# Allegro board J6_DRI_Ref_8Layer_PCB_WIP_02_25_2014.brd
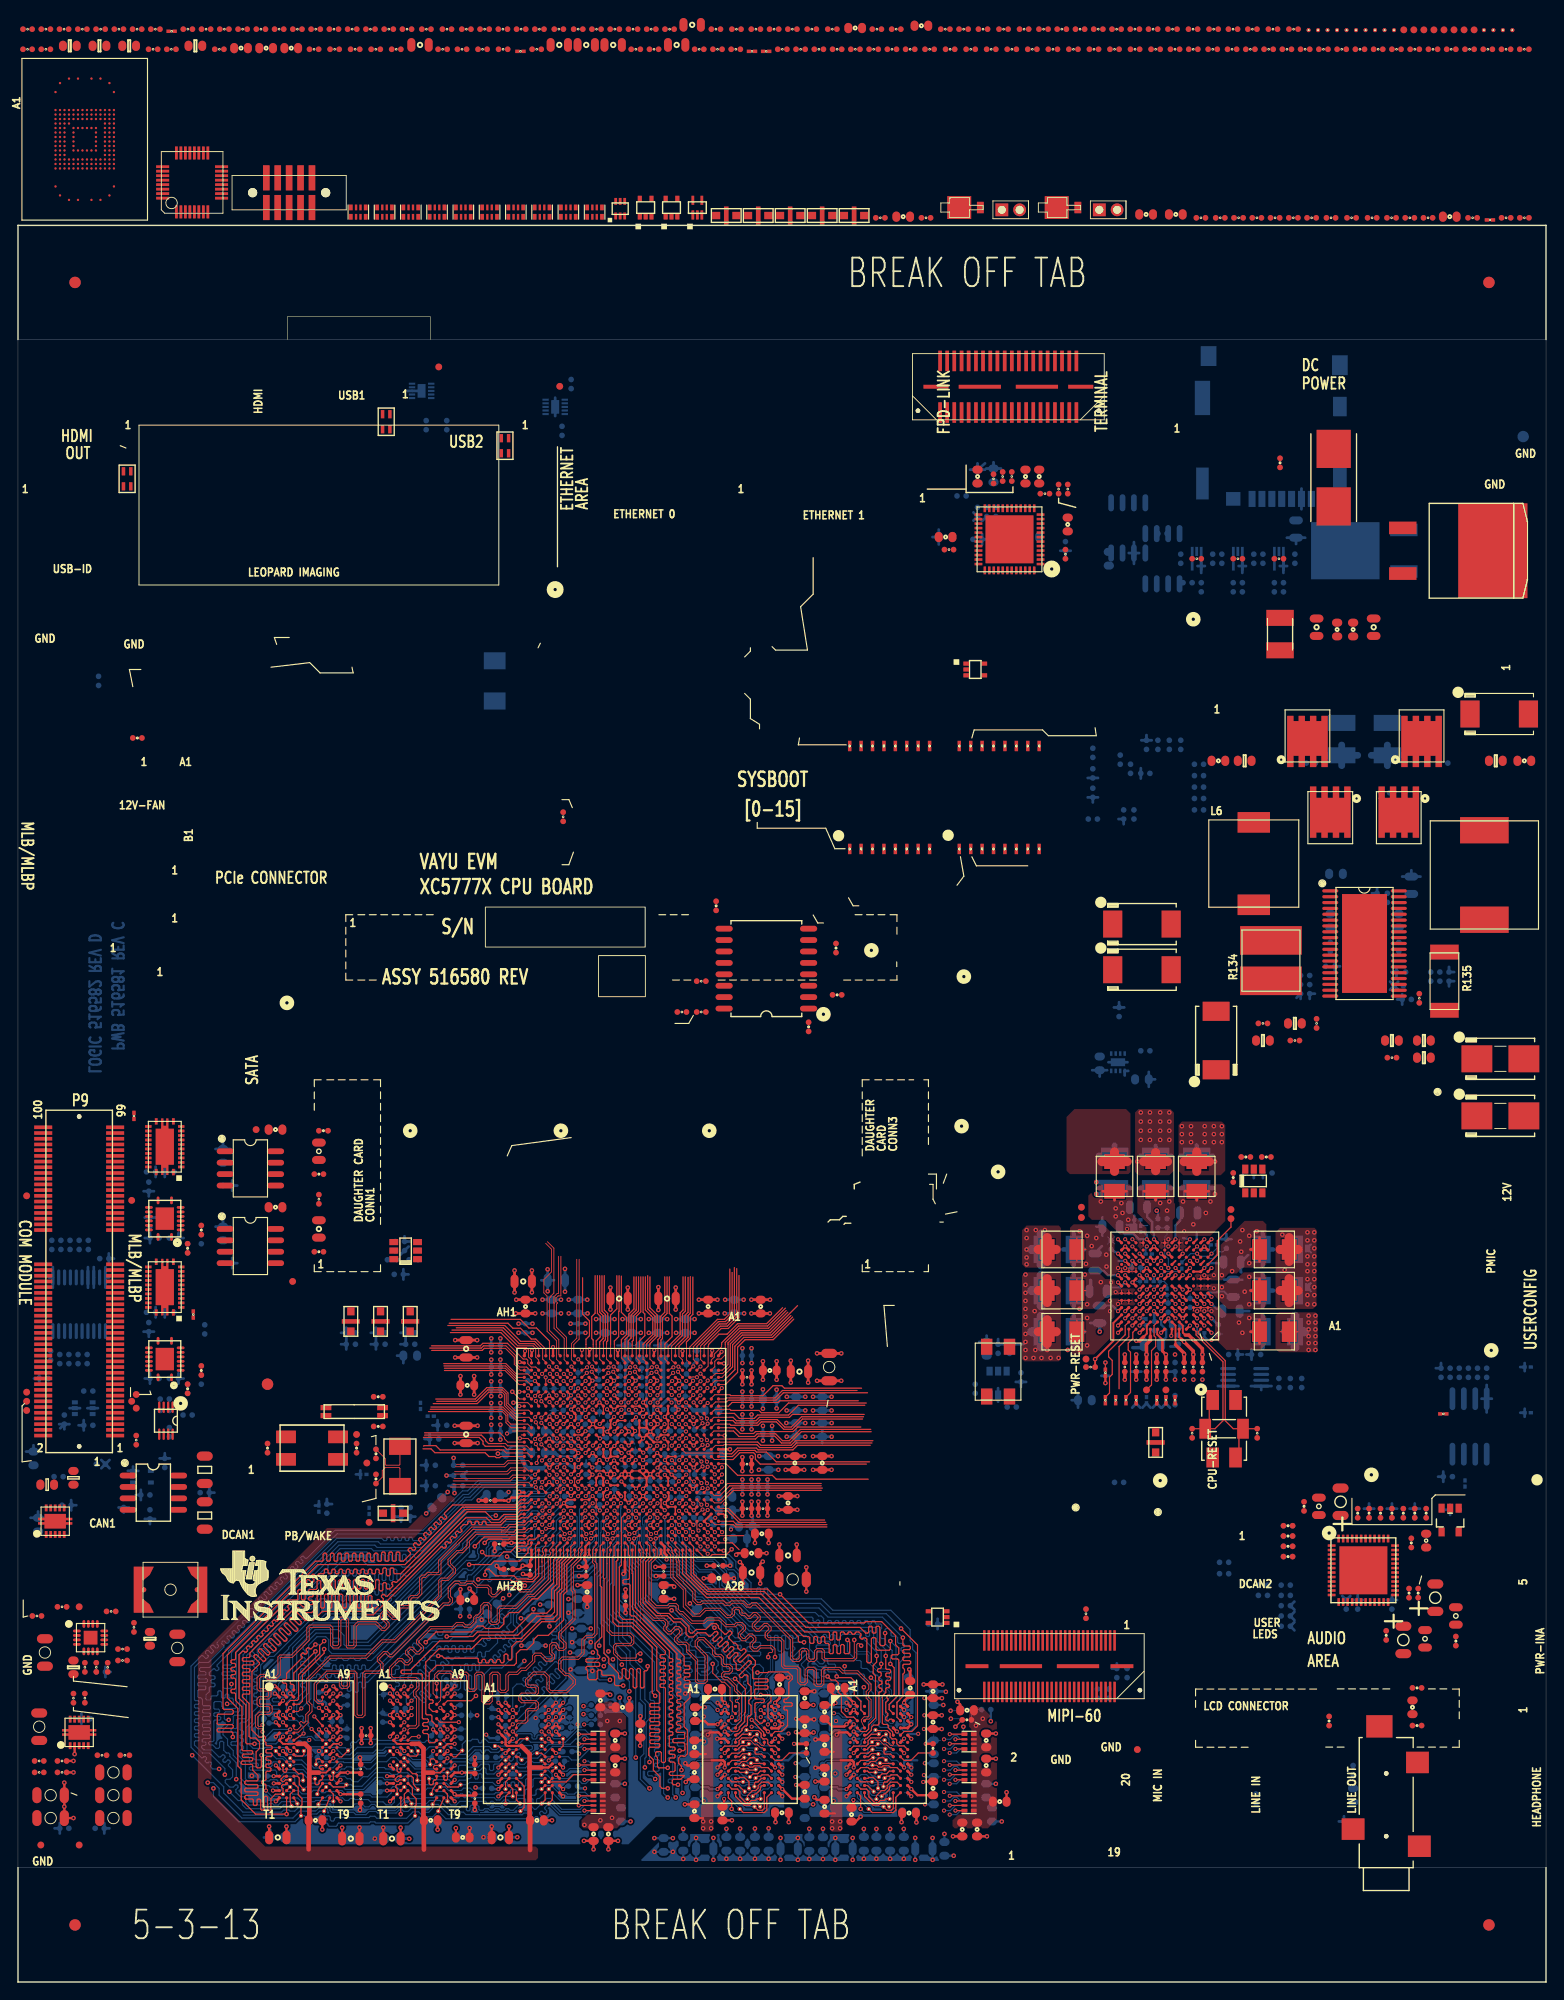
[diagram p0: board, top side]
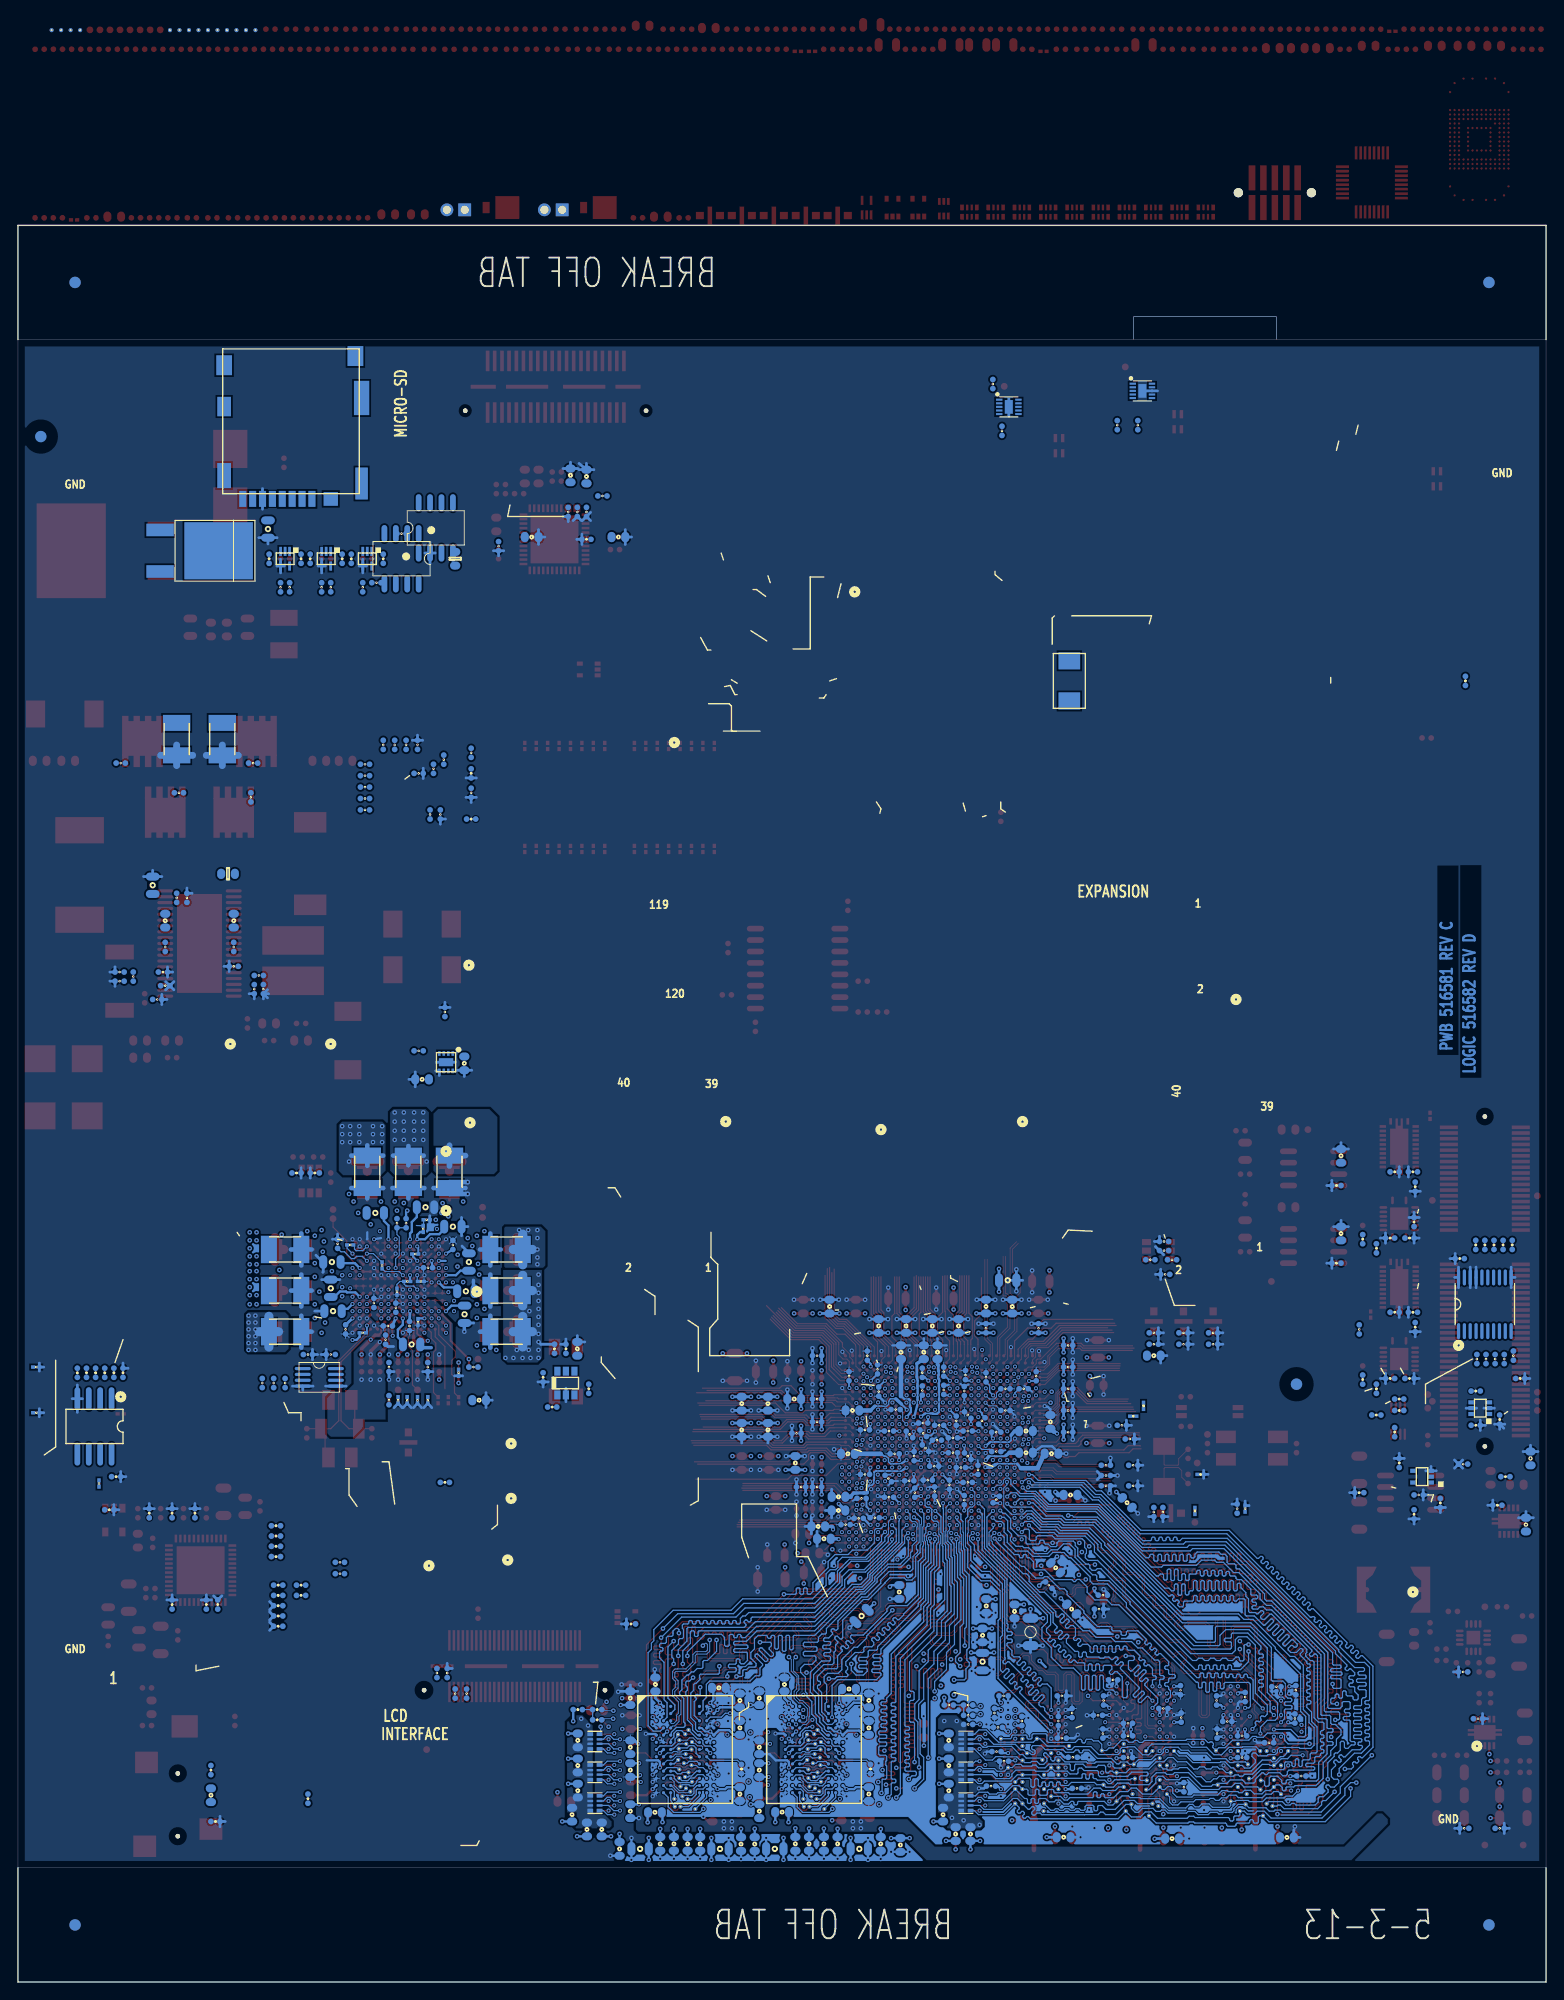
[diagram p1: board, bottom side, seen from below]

Outline 170 x 195.4 mm; copper layers: TOP, L2-GND1, L3-SIGNAL, L4-PWR1, L5-PWR2, L6-SIGNAL, L7-GND2, BOTTOM. Coordinates in mm from the lower left corner of the outline.
Outline path: 0,182.7 0,195.4 170,195.4 170,182.7 ; 0,182.7 0,12.7 ; 0,182.7 170,182.7 ; 0,12.7 0,0 170,0 170,12.7 ; 0,12.7 170,12.7 ; 170,12.7 170,182.7 ; 30,182.7 30,185.24 45.88,185.24 45.88,182.7

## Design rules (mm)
net group CON_USB1_DM: nets CON_USB1_DM H_USB1_DM
net group CON_USB1_DP: nets CON_USB1_DP H_USB1_DP
net group CON_USB2_DM: nets CON_USB2_DM H_USB2_DM
net group CON_USB2_DP: nets CON_USB2_DP H_USB2_DP
net group CPU_HDMI_TX0: nets H_HDMI_TX0+ H_HDMI_TX0-
net group CPU_HDMI_TX1: nets H_HDMI_TX1+ H_HDMI_TX1-
net group CPU_HDMI_TXC: nets H_HDMI_TXC+ H_HDMI_TXC-
net group DIFFPAIR0: nets H_DDR1_CLK0 H_DDR1_CLK0N
net group DIFFPAIR1: nets H_DDR1_DQS0 H_DDR1_DQSN0
net group DIFFPAIR2: nets H_DDR1_DQS1 H_DDR1_DQSN1
net group DIFFPAIR3: nets H_DDR1_DQS2 H_DDR1_DQSN2
net group DIFFPAIR4: nets H_DDR1_DQS3 H_DDR1_DQSN3
net group DIFFPAIR5: nets H_DDR1_DQS_ECC H_DDR1_DQSN_ECC
net group DIFFPAIR6: nets H_DDR2_CLK0 H_DDR2_CLK0N
net group DIFFPAIR7: nets H_DDR2_DQS3 H_DDR2_DQSN3
net group DIFFPAIR8: nets H_DDR2_DQS2 H_DDR2_DQSN2
net group DIFFPAIR9: nets H_DDR2_DQS1 H_DDR2_DQSN1
net group DIFFPAIR10: nets H_DDR2_DQS0 H_DDR2_DQSN0
net group HDMI_TX2: nets H_HDMI_TX2+ H_HDMI_TX2-
net group 100-OHM: nets H_MLBP_DAT_N H_MLBP_DAT_P H_MLBP_SIG_N H_MLBP_SIG_P H_OSC0_XIN H_OSC0_XOUT H_OSC1_RTN H_OSC1_XOUT H_OSCRTC_XIN H_OSCRTC_XOUT
net group CLK-2X: nets AIC_BCLK AIC_MCA3_ACLKX AIC_WCLK COMQ_MMC0_CLK CON_MMC1_CLK FM_I2S_CLK H_MLBP_CLK_N H_MLBP_CLK_P MCA1_ACLKX MCA7_CLKX MMC2_CLK MMC4_CLK PCM_CLK PMIC_32K_CLKOUT SLEEP_CLK
net group H_QSPI1_RTCLK: nets H_QSPI1_RTCLK H_QSPI1_SCLK_23254155 H_QSPI1_SCLK_S1_23254130
net group PWR_PH: nets H_USB1_DRV_VBUS H_USB2_DRV_VBUS N16995143 N17213676 N17213686 N17213736 N17213790 N17213808 N17213830 N17213836 N17213987 N17214061 N17214151 N17214159 N17214195 N17214201 N17214255 N17214311 N17214457 N17214615 N17214651 N17444583 N17444631 N17444633 N17444649 N17551928 N18507369 N18740603 N18740978 N18743331 N18763016 N18763017 N18763021 N19176689 N19176787 N21135894 N21136029 N21136035 N21136037 N21136043 N21136051 N21136104 N21136106 N21136118 N21136820 N21137001 N21137040 N21137042 N21137044 N21411928 N25164864 N25164868 N32742919 N32835273 N32916975 N33161549 N46501256 N167456600 N167457561 PMIC_GPIO_1 VAIC_AVDD_DAC3V3 VAIC_DRVDD_3V3 VAIC_DVDD_1V8 VAIC_IOVDD_3V3 VBUS_USB1_SW VBUS_USB2_SW VCAP_VBBLDO_GPU VCAP_VBBLDO_IVA VCAP_VBBLDO_MPU VCAP_VDDRAM_CORE1 VCAP_VDDRAM_CORE2 VCAP_VDDRAM_CORE3 VCAP_VDDRAM_CORE4 VCAP_VDDRAM_CORE5 VCAP_VDDRAM_DSPEVE1 VCAP_VDDRAM_DSPEVE2 VCAP_VDDRAM_IVA VCAP_VDDRAM_MPU1 VCAP_VDDRAM_MPU2 VDAC_3V3 VDDA_IVA_1V8 VDDA_PCI_1P8 VDDA_PHY_1V8 VDDA_PLL_1V8 VDDA_RTC VDDA_SATA_1P8 VDDSHV5 VDDSHV8 VMMC_3V3 VUSB_3V3
net group PWR_SP: nets EVM_12V GA1 GA2 GB1 GB2 H_POR_N LVL_SHIFT_V N17043188 N17213838 N17214057 N17214229 N17214562 N17214601 N17551455 N17681908 N18763019 N45361223 N45364158 PHA PHB TPS43351_GC2 VBUS_USB1 VBUS_USB2 VDDA_ANA VDDA_DEBUG_1V8 VDDA_HDMI VDDA_MPU_1V8 VDDA_VIDEO_1V8 VEVM_3V6 VEVM_5V0
net group VIDEO+: nets N21266752 N21266767 VIDEO+
net group VIDEO-: nets N21266761 N21266764 VIDEO-
nets with their own width: min track width 0.305; nets VEVM_3V3

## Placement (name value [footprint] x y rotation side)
C5  0.1uF  [C402-25]  109.55 167.46 90 top
C6  0.1uF  [C402-25]  110.57 167.46 90 top
C7  4.7uF  [C603-35X45]  112.09 167.46 90 top
C8  4.7uF  [C603-35X45]  113.61 167.46 90 top
C13  4.7uF  [C603-35X45]  116.79 162.13 90 top
C14  0.1uF  [C402-25]  131.14 158.32 0 top
C15  0.1uF  [C402-25]  135.71 158.32 0 top
C16  0.1uF  [C402-25]  140.28 158.32 0 top
C45  0.1uF  [C603-35X45]  146.76 150.45 90 top
C47  1uF  [C805-35X60]  144.48 150.7 90 top
C49  0.1uF  [C603-35X45]  148.54 150.45 90 top
C50  1uF  [C805-35X60]  150.83 150.7 90 top
C51  100uF,16V  [C7343-84X118]  164.8 141.05 0 top
C52  4.7uF  [C1210-70X102]  140.41 149.94 90 top
C60  330pF  [C603-35X45]  133.55 135.84 0 top
C61  330pF  [C603-35X45]  167.59 135.84 180 top
C62  22uF,25V, x5R  [C1210-70X102]  147.27 138.25 90 bottom
C63  22uF,25V, x5R  [C1210-70X102]  152.35 138.25 90 bottom
C67  0.1uF  [C402-25]  91.14 109.81 0 top
C71  100uF 10V  [C7343-84X118]  125.04 112.6 0 top
C72  47UF 16V  [C1210-C7343-DUAL]  164.92 102.69 0 top
C74  100uF 10V  [C7343-84X118]  133.3 104.73 90 top
C76  100pF  [C402-25]  142.06 104.73 180 top
C77  47UF 16V  [C1210-C7343-DUAL]  164.92 96.34 0 top
C78  100pF  [C402-25]  152.86 102.82 0 top
C79  10uF  [C603-35X45]  28.65 94.82 180 top
C80  0.1uF  [C402-25]  33.99 94.69 0 top
C86  10uF  [C603-35X45]  28.65 86.18 180 top
C87  0.1uF  [C402-25]  33.48 87.07 90 top
C89  0.1uF  [C402-6P6SPC]  56.46 72.72 90 bottom
C90  0.22uF  [C603-6P6SPC]  82.63 75.14 270 top
C91  1uF  [C603-6P6SPC]  89.48 61.42 90 bottom
C92  0.22uF  [C603-6P6SPC]  86.56 64.34 90 bottom
C93  0.47uF  [C603-6P6SPC]  86.44 57.74 90 top
C94  0.47uF  [C603-6P6SPC]  89.48 64.34 90 bottom
C95  1uF  [C603-6P6SPC]  86.56 61.42 90 bottom
C96  0.22uF  [C603-6P6SPC]  89.48 57.74 90 top
C99  2.2uF/0402/6.3V  [C402-25]  125.55 68.4 90 top
C100  0.1uF  [C402-25]  128.85 72.98 180 bottom
C101  2.2uF/0402/6.3V  [C402-25]  129.74 68.4 270 top
C102  2.2uF/0402/6.3V  [C402-25]  130.76 68.4 90 top
C103  2.2uF/0402/6.3V  [C402-25]  131.78 68.4 90 top
C104  10uF  [C805-35X60]  73.28 215.47 0 top
C105  2.2uF  [C603-6P6SPC]  83.64 68.02 180 top
C106  33pF  [C402-25]  40.08 65.1 180 top
C107  0.1uF  [C402-6P6SPC]  81.1 64.85 0 bottom
C108  0.47uF  [C603-6P6SPC]  49.99 66.37 0 top
C109  0.1uF  [C402-6P6SPC]  72.36 63.68 0 bottom
C110  0.1uF  [C402-25]  47.19 61.93 180 bottom
C111  1uF  [C603-6P6SPC]  56.46 75.14 270 top
C112  0.1uF  [C402-6P6SPC]  61.16 59.01 180 bottom
C113  33pF  [C402-25]  40.08 61.8 180 top
C115  12pF/0402/50V  [C402-25]  130.63 61.04 270 top
C116  12pF/0402/50V  [C402-25]  137.87 61.04 270 top
C117  0.1uF  [C402-25]  46.3 60.4 180 bottom
C118  0.1uF  [C402-6P6SPC]  53.16 70.82 180 bottom
C119  0.1uF  [C402-6P6SPC]  53.16 63.58 180 bottom
C123  18 pF  [C402-25]  27.76 59.39 90 top
C124  18 pF  [C402-25]  37.67 59.39 270 top
C126  18 pF  [C402-25]  39.83 58.75 270 top
C128  18 pF  [C402-25]  39.83 55.96 90 top
C130  10uF  [C1206-40X70-POL]  147.14 53.42 90 top
C131  0.1uF  [C402-25]  143.08 52.91 270 top
C132  0.1uF  [C402-25]  149.05 52.15 90 top
C133  4.7uF  [C603-35X45]  156.67 49.1 90 top
C134  0.1uF  [C402-25]  155.02 48.85 90 top
C136  0.22uF  [C603-35X45]  63.32 43.39 270 top
C137  0.1uF  [C402-25]  53.54 48.72 180 top
C138  0.1uF  [C402-25]  56.97 45.8 270 top
C139  0.1uF  [C402-25]  63.2 45.67 270 top
C140  22uF  [C1206-40X70]  57.35 38.94 270 bottom
C141  0.1uF  [C402-25]  154.76 43.26 90 top
C142  0.1uF  [C402-25]  155.78 43.26 90 top
C143  0.1uF  [C402-25]  52.55 53.57 180 top
C144  10uF  [C1206-40X70-POL]  157.68 42.75 90 top
C147  0.1uF  [C402-25]  67.59 42.37 270 top
C148  0.1uF  [C402-25]  54.56 45.93 180 top
C149  0.1uF  [C402-25]  10.36 41.23 180 top
C150  NP  [C402-25]  12.9 39.45 270 top
C151  0.1uF  [C402-25]  152.22 38.56 270 top
C152  10uF  [C1206-40X70-POL]  154.13 38.05 270 top
C153  0.1uF  [C402-25]  159.97 37.92 270 top
C154  47uF  [C1206-40X70]  17.73 37.16 270 top
C155  4700pF  [C402-25]  11.63 37.04 0 top
C156  10uF  [C1206-40X70]  3 36.65 270 top
C157  12pF  [C402-25]  9.98 35 90 top
C158  0.22uF  [C603-35X45]  84.73 33.1 90 top
C159  0.22uF  [C603-35X45]  99.26 32.72 90 top
C160  0.22uF  [C603-35X45]  77.55 32.59 180 top
C161  0.22uF  [C603-35X45]  91.21 32.72 180 top
C162  0.22uF  [C603-35X45]  87.53 31.57 90 top
C163  0.22uF  [C603-35X45]  101.8 32.34 90 top
C164  0.22uF  [C603-35X45]  64.8 31.32 90 top
C165  0.22uF  [C603-35X45]  67.26 30.56 0 top
C166  0.22uF  [C603-35X45]  105.59 30.23 180 top
C167  0.22uF  [C603-35X45]  109.22 20.07 0 top
C168  2.2uF  [C603-35X45]  155.14 30.56 270 top
C169  0.22uF  [C603-35X45]  75.34 29.8 90 top
C170  0.22uF  [C603-35X45]  89.74 30.05 90 top
C171  0.22uF  [C603-35X45]  87.53 28.45 90 top
C172  0.22uF  [C603-35X45]  101.8 28.91 90 top
C173  0.1uF  [C402-25]  145.87 29.03 90 top
C174  10uF  [C1206-40X70]  2.36 28.4 90 top
C175  0.22uF  [C603-35X45]  66.45 26.88 90 top
C176  0.22uF  [C603-35X45]  107.72 26.88 90 top
C177  0.22uF  [C603-35X45]  75.26 26.11 90 top
C178  0.22uF  [C603-35X45]  89.74 26.37 90 top
C179  10pF  [C402-25]  11.89 25.22 180 top
C180  0.22uF  [C603-35X45]  66.45 24.08 90 top
C181  0.22uF  [C603-35X45]  107.72 24.08 90 top
C182  0.22uF  [C402-25]  38.13 23.7 90 top
C183  0.22uF  [C402-25]  50.83 23.7 90 top
C184  0.22uF  [C603-35X45]  75.26 23.32 90 top
C185  0.22uF  [C603-35X45]  89.74 23.07 90 top
C186  1000pF  [C402-25]  2.36 23.32 0 top
C187  0.001uF  [C402-25]  4.9 23.32 0 top
C188  10uF  [C1206-40X70]  10.62 23.32 180 top
C189  0.22uF  [C603-35X45]  87.53 21.16 90 top
C190  0.22uF  [C603-35X45]  101.8 21.54 90 top
C191  10uF  [C1206-40X70]  3.63 20.78 0 top
C192  10uF  [C1206-40X70]  10.62 20.78 180 top
C193  0.22uF  [C402-25]  38.13 20.4 270 top
C194  0.22uF  [C402-25]  50.83 20.4 270 top
C195  0.22uF  [C603-35X45]  84.99 18.82 0 top
C196  0.22uF  [C603-35X45]  99.14 18.8 0 top
C197  0.22uF  [C603-35X45]  75.26 19 90 top
C198  0.22uF  [C603-35X45]  89.74 19.51 90 top
C199  0.22uF  [C603-35X45]  78.38 18.75 270 top
C200  0.22uF  [C603-35X45]  92.74 18.62 270 top
C201  10uF  [C1206-40X70]  3.63 18.24 0 top
C202  10uF  [C1206-40X70]  10.62 18.24 180 top
C203  0.22uF  [C603-35X45]  33.1 17.99 0 top
C204  0.22uF  [C603-35X45]  45.92 17.99 0 top
C205  0.22uF  [C603-35X45]  57.73 17.99 0 top
C206  0.22uF  [C603-35X45]  64.03 16.46 270 top
C207  0.22uF  [C603-35X45]  65.68 16.46 270 top
C208  0.22uF  [C603-35X45]  105.05 16.97 270 top
C209  0.22uF  [C603-35X45]  106.71 16.97 270 top
C210  10uF  [C805-35X60]  28.91 16.08 180 top
C211  10uF  [C805-35X60]  37.03 15.95 0 top
C212  10uF  [C805-35X60]  41.61 15.95 180 top
C213  10uF  [C603-35X45]  49.48 16.08 0 top
C214  10uF  [C805-35X60]  53.67 16.08 180 top
C228  4.7uF  [C603-35X45]  108.53 167.59 90 bottom
C229  4.7uF  [C603-35X45]  106.76 167.46 90 bottom
C231  0.1uF  [C402-25]  108.79 163.53 270 bottom
C232  0.1uF  [C402-25]  107.77 163.53 270 bottom
C233  10uF  [C805-35X60]  142.19 161.62 270 bottom
C234  4.7uF  [C603-35X45]  112.85 160.73 180 bottom
C235  4.7uF  [C603-35X45]  103.2 160.73 180 bottom
C236  0.1uF  [C402-25]  106.76 160.48 0 bottom
C269  0.1uF  [C402-25]  125.55 137.62 90 bottom
C273  4.7uF  [C402-25]  125.43 134.44 180 bottom
C274  0.22uF  [C402-25]  119.58 134.44 270 bottom
C280  2.2uF  [C402-25]  119.58 132.29 270 bottom
C290  0.22uF  [C402-25]  123.01 129.87 270 bottom
C293  0.1uF  [C402-25]  76.02 111.33 180 top
C295  4.7uF/25V  [C805-35X60]  155.02 122 270 bottom
C299  .22uF,50V  [C603-35X45]  153.62 118.06 90 bottom
C300  .22uF,50V  [C603-35X45]  146 118.06 90 bottom
C301  0.01uF  [C402-25]  153.62 115.14 270 bottom
C302  0.01uF  [C402-25]  146 115.14 270 bottom
C303  2000pF  [C402-25]  157.18 111.84 90 bottom
C304  39pf  [C402-25]  158.7 112.35 180 bottom
C305  0.01uF  [C402-25]  146 112.98 0 bottom
C306  0.01uF  [C402-25]  153.87 112.35 180 bottom
C307  2700pF  [C402-25]  143.21 111.97 0 bottom
C309  56pf  [C402-25]  143.71 110.44 90 bottom
C314  1000pF  [C402-25]  154.51 109.3 180 bottom
C318  220pF 50V  [C603-35X45]  125.04 100.41 0 bottom
C319  NP  [C603-35X45]  120.35 102.19 270 bottom
C325  10uF  [C603-35X45]  22.81 91.9 90 bottom
C326  47uF/10V  [C1210-70X102]  131.14 90.12 90 bottom
C327  47uF/10V  [C1210-70X102]  126.57 90.12 90 bottom
C328  47uF/10V  [C1210-70X102]  122 90.12 90 bottom
C329  NP  [C402-25]  139.01 89.99 180 bottom
C330  0.1uF  [C402-25]  136.98 89.99 0 bottom
C331  0.1uF  [C402-25]  16.84 90.12 180 bottom
C332  0.1uF  [C402-25]  14.81 90.12 0 bottom
C335  0.1uF  [C402-25]  14.55 88.47 270 bottom
C338  4.7uF 10V  [C805-35X60]  130.25 85.55 180 bottom
C340  10uF  [C603-35X45]  22.81 83.26 90 bottom
C341  4.7uF 10V  [C805-35X60]  124.66 86.18 0 bottom
C342  4.7uF 10V  [C805-35X60]  121.62 84.03 0 bottom
C344  0.1uF  [C402-25]  17.35 82.76 0 bottom
C345  0.1uF  [C402-25]  15.19 82.76 180 bottom
C346  2.2uF/0402/6.3V  [C402-25]  121.62 81.99 270 bottom
C348  NP  [C402-25]  42.49 82.37 0 bottom
C349  47uF/10V  [C1210-70X102]  140.28 81.49 0 bottom
C350  47uF/10V  [C1210-70X102]  115.65 81.49 180 bottom
C351  0.1uF  [C402-25]  9.6 80.47 0 bottom
C352  2.2uF/0402/6.3V  [C402-25]  124.38 79.45 0 bottom
C353  4.7uF 10V  [C805-35X60]  135.08 80.09 180 bottom
C354  4.7uF 10V  [C805-35X60]  119.84 80.09 270 bottom
C355  10uF  [C805-35X60]  63.22 215.47 0 top
C356  22uF  [C1206-6P6SPC]  90.25 68.4 270 top
C357  10uF  [C805-35X60]  56.21 77.93 0 top
C358  0.1uF  [C402-25]  42.37 78.72 0 bottom
C359  2.2uF  [C603-6P6SPC]  83.52 57.74 270 bottom
C360  4.7uF  [C805-6P6SPC]  86.94 67.9 180 top
C363  0.1uF  [C402-6P6SPC]  69.29 62.18 180 bottom
C364  0.1uF  [C402-6P6SPC]  69.39 65.79 270 bottom
C365  0.1uF  [C402-6P6SPC]  81.1 52.66 0 top
C366  0.1uF  [C402-6P6SPC]  38.73 27.41 0 top
C367  1uF  [C603-6P6SPC]  85.67 53.29 90 top
C368  0.1uF  [C402-6P6SPC]  66.37 55.32 90 bottom
C369  0.1uF  [C402-6P6SPC]  81.1 62.31 0 bottom
C370  0.1uF  [C402-6P6SPC]  81.1 57.61 180 top
C371  0.1uF  [C402-25]  53.16 65.99 180 bottom
C372  0.1uF  [C402-6P6SPC]  62.31 72.72 90 bottom
C373  1uF  [C603-6P6SPC]  79.71 75.14 270 bottom
C374  0.47uF  [C603-6P6SPC]  76.78 75.14 270 top
C375  4.7uF 10V  [C805-35X60]  135.2 77.17 270 bottom
C376  4.7uF 10V  [C805-35X60]  120.17 76.84 0 bottom
C377  47uF/10V  [C1210-70X102]  140.28 76.91 0 bottom
C378  47uF/10V  [C1210-70X102]  115.65 76.91 180 bottom
C379  4.7uF 10V  [C805-35X60]  120.32 74.27 90 bottom
C380  4.7uF 10V  [C805-35X60]  134.95 74.63 180 bottom
C381  2.2uF/0402/6.3V  [C402-25]  127.97 75.01 270 bottom
C382  10uF  [C805-35X60]  49.86 60.91 90 top
C384  0.1uF  [C402-6P6SPC]  70.31 58.5 90 bottom
C385  0.1uF  [C402-6P6SPC]  70.84 55.76 0 bottom
C386  0.1uF  [C402-6P6SPC]  67.51 61.93 180 bottom
C387  0.1uF  [C402-6P6SPC]  83.39 61.04 0 bottom
C388  0.1uF  [C402-6P6SPC]  64.72 65.74 270 bottom
C389  0.1uF  [C402-6P6SPC]  82.88 52.66 0 top
C390  0.1uF  [C402-6P6SPC]  69.29 61.04 225 bottom
C391  0.1uF  [C402-6P6SPC]  68.78 55.83 180 bottom
C392  0.1uF  [C402-6P6SPC]  82.88 55.07 180 bottom
C393  1uF  [C603-6P6SPC]  68.28 72.98 270 bottom
C394  0.47uF  [C603-6P6SPC]  65.35 72.98 270 bottom
C395  0.22uF  [C603-6P6SPC]  74.24 72.98 270 bottom
C396  0.1uF  [C402-6P6SPC]  81.1 55.07 0 bottom
C399  0.1uF  [C402-25]  60.15 63.58 0 bottom
C400  0.1uF  [C402-25]  60.15 65.99 0 bottom
C401  0.1uF  [C402-25]  137.34 217.23 0 top
C402  0.1uF  [C402-25]  128.45 217.23 0 top
C403  2.2uF/0402/6.3V  [C402-25]  133.55 72.6 90 bottom
C404  0.1uF  [C402-25]  16.84 74.5 180 bottom
C405  0.1uF  [C402-25]  14.81 74.5 0 bottom
C406  10uF  [C805-35X60]  49.86 70.44 90 top
C407  2.2uF/0402/6.3V  [C402-25]  129.11 71.45 90 bottom
C408  2.2uF/0402/6.3V  [C402-25]  130.4 75.54 270 bottom
C409  47uF/10V  [C1210-70X102]  140.28 72.34 0 bottom
C410  47uF/10V  [C1210-70X102]  115.65 72.34 180 bottom
C411  0.1uF  [C402-25]  14.55 72.85 270 bottom
C412  0.1uF  [C402-25]  42.09 214.99 0 top
C413  0.01uF  [C402-25]  35.23 214.99 0 top
C414  0.1uF  [C402-25]  39.8 214.99 0 top
C415  0.1uF  [C402-25]  43.64 72.21 0 bottom
C416  0.1uF  [C402-25]  40.34 72.21 180 bottom
C417  0.1uF  [C402-25]  37.03 72.21 180 bottom
C418  1uF  [C603-35X45]  30.4 215.12 0 top
C419  0.001uF  [C402-25]  148.37 196.24 0 top
C420  0.01uF  [C402-25]  32.94 214.99 0 top
C421  220pF 50V  [C603-35X45]  107.77 70.44 90 bottom
C422  0.01uF  [C402-25]  43.64 70.94 180 bottom
C423  0.001uF  [C402-25]  40.34 70.94 180 bottom
C424  0.001uF  [C402-25]  37.03 70.94 180 bottom
C425  0.001uF  [C402-25]  146.08 196.24 0 top
C426  1uF  [C603-35X45]  27.61 215.12 0 top
C427  0.001uF  [C402-25]  131.61 196.24 0 top
C429  1uF  [C603-35X45]  43.64 69.67 180 bottom
C430  2.2uF/0402/6.3V  [C402-25]  128.73 68.4 270 bottom
C431  2.2uF/0402/6.3V  [C402-25]  127.71 68.4 270 top
C432  4.7uF 10V  [C805-35X60]  126.21 70.92 0 bottom
C433  2.2uF/0402/6.3V  [C402-25]  124.41 68.4 270 top
C434  0.1uF  [C402-25]  124.41 68.4 90 bottom
C435  0.1uF  [C402-25]  135.2 69.8 0 bottom
C436  10uF  [C805-35X60]  66.22 215.47 0 top
C437  0.1uF  [C402-25]  75.51 69.67 270 bottom
C438  0.1uF  [C402-25]  141.91 217.23 0 top
C439  0.001uF  [C402-25]  60.17 217.23 0 top
C440  10uF  [C805-35X60]  60.22 215.47 0 top
C441  0.1uF  [C402-25]  111.58 67.26 270 bottom
C442  0.1uF  [C402-25]  67.01 67.9 90 bottom
C443  0.1uF  [C402-25]  64.59 67.52 90 bottom
C444  0.1uF  [C402-25]  74.37 68.15 270 bottom
C445  0.1uF  [C402-25]  69.39 67.77 90 bottom
C446  0.1uF  [C402-25]  17.35 67.13 0 bottom
C447  0.1uF  [C402-25]  15.19 67.13 180 bottom
C448  0.1uF  [C402-25]  2.87 67.13 180 bottom
C449  0.1uF  [C402-25]  62.31 67.26 90 bottom
C450  0.1uF  [C402-25]  37.52 214.99 0 top
C451  0.01uF  [C402-25]  161.83 196.24 0 top
C453  4.7uF  [C805-6P6SPC]  72.21 76.02 180 top
C454  0.1uF  [C402-25]  56.72 67.39 90 bottom
C455  0.1uF  [C402-25]  77.55 67.39 270 bottom
C456  2.2uF  [C603-6P6SPC]  71.2 72.98 270 bottom
C457  0.1uF  [C402-25]  67.01 65.86 90 bottom
C458  0.1uF  [C402-25]  74.24 65.67 90 bottom
C459  10uF/6.3V  [C603-35X45]  118.69 64.72 0 bottom
C460  10uF  [C805-6P6SPC]  59.89 78.06 180 bottom
C461  0.1uF  [C402-25]  65.61 62.44 90 bottom
C462  1uF  [C603-35X45]  77.17 63.58 0 bottom
C463  0.1uF  [C402-6P6SPC]  81.1 67.26 0 top
C464  0.1uF  [C402-25]  58.12 65.99 180 bottom
C465  0.22uF  [C603-6P6SPC]  83.64 64.85 180 bottom
C466  0.1uF  [C402-6P6SPC]  64.34 58.5 225 bottom
C467  0.1uF  [C402-25]  62.76 62.41 315 bottom
C468  1uF  [C603-35X45]  67.7 70.06 90 bottom
C469  0.1uF  [C402-6P6SPC]  70.82 60.91 45 bottom
C470  0.1uF  [C402-25]  139.62 217.23 0 top
C471  0.1uF  [C402-25]  73.18 56.01 225 bottom
C472  0.1uF  [C402-25]  5.16 62.56 270 bottom
C473  0.1uF  [C402-6P6SPC]  53.16 68.4 180 bottom
C474  0.1uF  [C402-6P6SPC]  53.16 61.17 180 bottom
C475  0.1uF  [C402-6P6SPC]  64.34 63.07 45 bottom
C477  1uF  [C603-35X45]  69.23 70.06 90 bottom
C478  0.47uF  [C603-6P6SPC]  62.31 75.14 270 bottom
C479  0.1uF  [C402-25]  7.82 61.93 180 bottom
C480  1uF  [C603-35X45]  55.14 62.31 90 bottom
C481  1uF  [C603-35X45]  71.77 70.06 90 bottom
C482  0.1uF  [C402-25]  75.77 61.42 0 bottom
C483  1uF  [C603-6P6SPC]  59.39 75.14 270 bottom
C484  0.1uF  [C402-25]  73.1 61.29 0 bottom
C485  0.1uF  [C402-25]  65.99 60.53 0 bottom
C486  0.1uF  [C402-25]  61.16 61.17 180 bottom
C487  4.7uF  [C805-6P6SPC]  66.88 76.02 180 top
C489  0.1uF  [C402-25]  64.34 61.29 0 bottom
C490  1uF  [C603-35X45]  24.82 215.12 0 top
C491  0.01uF  [C402-25]  67.77 60.28 0 bottom
C492  0.1uF  [C402-6P6SPC]  81.1 69.67 0 bottom
C493  10uF  [C805-35X60]  44.73 215.47 0 top
C494  0.1uF  [C402-25]  133.02 217.23 0 top
C495  0.1uF  [C402-6P6SPC]  69.04 59.39 225 bottom
C496  0.1uF  [C402-25]  130.73 217.23 0 top
C497  0.001uF  [C402-25]  65.99 58.88 180 bottom
C498  0.1uF  [C402-6P6SPC]  64.34 55.58 0 bottom
C500  0.1uF  [C402-25]  75.77 56.47 0 bottom
C501  1uF  [C603-35X45]  57.86 61.29 180 bottom
C502  0.1uF  [C402-25]  72.47 58.75 0 bottom
C503  10uF  [C603-35X45]  1.73 58.24 90 bottom
C504  1uF  [C603-35X45]  77.67 58.75 0 bottom
C506  1uF  [C603-35X45]  57.86 58.88 180 bottom
C507  0.1uF  [C402-25]  68.07 57.38 0 bottom
C508  0.1uF  [C402-25]  65.1 57.23 0 bottom
C509  1uF  [C603-35X45]  78.71 53.98 0 bottom
C510  0.01uF  [C402-25]  48.97 57.48 180 bottom
C511  0.001uF  [C402-25]  45.92 57.48 180 bottom
C512  1uF  [C603-35X45]  55.02 58.78 180 bottom
C513  0.1uF  [C402-25]  159.08 56.21 0 bottom
C514  0.1uF  [C402-25]  48.97 56.34 180 bottom
C515  5.6pF  [C402-25]  4.52 56.21 0 bottom
C516  1uF  [C603-35X45]  80.34 49.3 0 bottom
C517  1uF  [C603-35X45]  80.98 50.68 0 bottom
C518  0.1uF  [C402-25]  63.2 56.97 270 bottom
C519  1uF  [C603-35X45]  52.91 54.18 180 bottom
C520  1uF  [C603-35X45]  78.71 52.45 0 bottom
C521  0.1uF  [C402-25]  48.97 55.2 180 bottom
C522  0.1uF  [C402-25]  45.92 55.2 180 bottom
C523  0.1uF  [C402-25]  53.98 214.99 0 top
C524  0.1uF  [C402-25]  68.02 54.56 90 bottom
C525  4700pF  [C402-25]  20.78 54.43 0 bottom
C526  0.1uF  [C402-25]  76.15 53.8 0 bottom
C527  0.1uF  [C402-25]  14.17 54.18 180 bottom
C528  0.1uF  [C402-25]  73.1 53.93 0 bottom
C529  1uF  [C603-35X45]  54.56 46.08 225 bottom
C530  0.1uF  [C402-25]  64.72 53.61 90 bottom
C531  0.1uF  [C402-25]  11.76 53.29 270 bottom
C532  0.001uF  [C402-25]  5.41 53.04 0 bottom
C535  1000pF  [C402-25]  34.37 52.66 90 bottom
C536  1uF  [C402-25]  159.84 52.53 180 bottom
C537  0.1uF  [C402-25]  74.69 51.64 0 bottom
C538  0.001uF  [C402-25]  43.64 52.28 270 bottom
C539  0.1uF  [C402-25]  42.62 52.28 270 bottom
C540  0.1uF  [C402-25]  14.68 52.02 270 bottom
C541  0.1uF  [C402-25]  76.47 51.58 0 bottom
C542  0.1uF  [C402-25]  77.93 50.88 180 bottom
C545  0.1uF  [C402-25]  111.94 217.23 0 top
C546  2.2uF  [C603-35X45]  2.24 50.88 90 bottom
C548  0.22uF  [C603-35X45]  71.83 43.39 270 top
C549  0.1uF  [C402-25]  61.16 53.67 135 bottom
C550  1000pF  [C402-25]  88.32 217.23 0 top
C553  1000pF  [C402-25]  90.6 217.23 0 top
C556  0.22uF  [C603-35X45]  82.75 49.86 0 top
C557  0.22uF  [C603-35X45]  49.99 42.5 180 top
C558  0.1uF  [C402-25]  138.51 44.15 0 bottom
C559  0.1uF  [C402-25]  77.93 46.31 0 top
C560  0.22uF  [C603-35X45]  46.61 53.32 225 bottom
C561  0.22uF  [C603-35X45]  71.96 43.39 270 bottom
C562  22uF  [C1206-40X70]  86.18 44.78 0 top
C563  0.1uF  [C402-25]  49.3 43.03 180 bottom
C564  0.22uF  [C603-35X45]  62.28 41.84 270 bottom
C565  0.1uF  [C402-25]  152.86 41.99 90 bottom
C566  0.1uF  [C402-25]  149.05 41.99 90 bottom
C567  0.1uF  [C402-25]  147.78 41.99 90 bottom
C568  0.1uF  [C402-25]  141.05 41.86 0 bottom
C569  1uF  [C603-35X45]  52.78 41.48 225 bottom
C570  0.1uF  [C402-25]  49.73 41.48 180 bottom
C571  0.22uF  [C603-35X45]  59.13 41.23 270 bottom
C572  4.7uF  [C805-35X60]  76.15 40.72 315 bottom
C573  0.1uF  [C402-25]  101.8 39.83 0 bottom
C574  0.1uF  [C402-25]  70.23 54.43 90 bottom
C575  NP  [C402-25]  141.05 39.58 0 bottom
C576  1uF  [C603-35X45]  62.69 38.56 270 bottom
C577  4.7uF  [C805-35X60]  62.69 35.64 270 bottom
C578  0.1uF  [C402-25]  55.32 44.15 225 bottom
C579  3300pf  [C402-25]  9.22 34.5 180 bottom
C580  0.22uF  [C402-25]  48.16 33.61 0 bottom
C581  0.22uF  [C603-35X45]  99.09 33.1 90 bottom
C582  0.22uF  [C603-35X45]  84.73 33.1 90 bottom
C583  0.22uF  [C402-25]  30 32.84 0 bottom
C584  0.1uF  [C402-25]  71.83 45.67 270 top
C585  0.22uF  [C603-35X45]  92.02 32.72 180 bottom
C586  0.22uF  [C603-35X45]  77.55 32.59 180 bottom
C587  0.22uF  [C402-25]  40.67 32.46 270 bottom
C588  0.22uF  [C402-25]  27.84 32.46 270 bottom
C589  4.7uF  [C805-35X60]  85.67 47.45 0 top
C590  0.22uF  [C402-25]  60.35 31.83 180 bottom
C591  0.22uF  [C402-25]  53.87 31.83 180 bottom
C592  0.22uF  [C603-35X45]  101.88 31.57 90 bottom
C593  0.22uF  [C603-35X45]  87.53 31.57 90 bottom
C594  0.22uF  [C402-25]  33.48 31.7 270 bottom
C595  0.22uF  [C603-35X45]  89.69 31.32 90 bottom
C596  0.22uF  [C603-35X45]  75.34 31.32 90 bottom
C597  0.22uF  [C402-25]  49.23 31.32 90 bottom
C598  0.22uF  [C402-25]  36.65 31.32 90 bottom
C599  0.1uF  [C402-25]  66.45 30.81 0 bottom
C600  0.22uF  [C402-25]  42.57 30.43 180 bottom
C601  0.1uF  [C402-25]  107.72 30.3 0 bottom
C602  0.22uF  [C402-25]  61.37 29.92 270 bottom
C603  0.22uF  [C402-25]  52.73 29.92 90 bottom
C605  0.22uF  [C402-25]  27.94 29.31 90 bottom
C606  0.22uF  [C402-25]  40.59 29.42 90 bottom
C607  0.1uF  [C402-25]  7.57 29.29 0 bottom
C608  0.22uF  [C402-25]  58.32 29.03 90 bottom
C609  0.22uF  [C402-25]  54.25 29.03 90 bottom
C610  0.22uF  [C402-25]  49.86 29.67 0 bottom
C611  0.22uF  [C402-25]  35.46 28.98 180 bottom
C612  0.22uF  [C402-25]  46.51 28.78 0 bottom
C613  0.22uF  [C402-25]  30.81 26.62 0 bottom
C614  0.22uF  [C402-25]  60.99 28.32 0 bottom
C615  0.22uF  [C603-35X45]  89.69 28.27 90 bottom
C616  0.22uF  [C603-35X45]  75.34 28.27 90 bottom
C617  0.22uF  [C603-35X45]  53.67 16.11 180 bottom
C618  0.22uF  [C603-35X45]  41.61 15.95 180 bottom
C619  0.22uF  [C603-35X45]  28.83 16.08 180 bottom
C621  0.22uF  [C402-25]  49.3 27.64 90 bottom
C622  0.22uF  [C402-25]  36.6 27.64 90 bottom
C623  0.22uF  [C402-25]  46.51 27.38 0 bottom
C624  0.22uF  [C402-25]  33.81 27.38 0 bottom
C625  0.22uF  [C402-25]  53.87 27.13 180 bottom
C626  0.22uF  [C603-35X45]  107.72 26.88 90 bottom
C627  0.22uF  [C603-35X45]  66.45 26.88 90 bottom
C628  0.22uF  [C603-35X45]  101.88 26.11 90 bottom
C629  0.22uF  [C603-35X45]  87.53 26.11 90 bottom
C630  0.22uF  [C603-35X45]  71.83 15.24 270 bottom
C631  0.22uF  [C603-35X45]  69.24 27.97 90 top
C632  0.22uF  [C402-25]  61.14 25.63 0 bottom
C633  0.22uF  [C402-25]  52.65 25 180 bottom
C634  0.22uF  [C603-35X45]  107.72 24.08 90 bottom
C635  0.22uF  [C603-35X45]  66.45 24.08 90 bottom
C636  0.22uF  [C603-35X45]  101.88 23.57 270 bottom
C637  0.22uF  [C603-35X45]  87.53 23.57 270 bottom
C638  0.22uF  [C402-25]  27.23 22.91 180 bottom
C639  0.22uF  [C402-25]  40.28 21.67 90 bottom
C640  0.22uF  [C402-25]  61.75 21.8 0 bottom
C641  0.22uF  [C402-25]  52.2 21.54 180 bottom
C642  0.22uF  [C603-35X45]  107.72 21.29 90 bottom
C643  0.22uF  [C603-35X45]  66.45 21.29 90 bottom
C644  0.22uF  [C603-35X45]  89.69 20.91 270 bottom
C645  0.22uF  [C603-35X45]  75.34 20.91 270 bottom
C647  2.2uF  [C603-35X45]  148.54 20.78 270 bottom
C648  0.1uF  [C402-25]  137.74 20.4 90 bottom
C649  0.22uF  [C603-35X45]  99.14 18.87 0 bottom
C650  0.22uF  [C603-35X45]  84.99 18.9 0 bottom
C651  0.22uF  [C603-35X45]  101.88 19 90 bottom
C652  0.22uF  [C603-35X45]  87.53 19 90 bottom
C653  0.22uF  [C603-35X45]  108.36 18.62 270 bottom
C654  0.22uF  [C603-35X45]  67.08 18.62 270 bottom
C655  1uF  [C603-35X45]  81.61 47.7 180 top
C656  1uF  [C603-35X45]  77.98 44.91 0 top
C657  4.7uF  [C805-35X60]  81.61 45.54 180 top
C658  0.1uF  [C402-25]  9.09 17.1 180 bottom
C659  0.1uF  [C402-25]  5.16 17.1 0 bottom
C660  0.22uF  [C603-35X45]  106.71 16.97 270 bottom
C661  0.22uF  [C603-35X45]  105.05 16.97 270 bottom
C662  0.22uF  [C603-35X45]  65.68 16.46 270 bottom
C663  0.22uF  [C603-35X45]  64.03 16.46 270 bottom
C664  0.22uF  [C603-35X45]  103.07 14.81 270 bottom
C665  10uF  [C805-35X60]  100.79 14.81 0 bottom
C666  0.22uF  [C603-35X45]  98.55 15.37 270 bottom
C667  0.22uF  [C603-35X45]  97.03 15.37 270 bottom
C668  0.22uF  [C603-35X45]  95.5 15.37 270 bottom
C669  0.22uF  [C603-35X45]  94.11 15.37 270 bottom
C670  10uF  [C805-35X60]  91.9 14.81 180 bottom
C671  0.22uF  [C603-35X45]  89.56 15.34 270 bottom
C672  0.22uF  [C603-35X45]  88.04 15.34 270 bottom
C673  10uF  [C805-35X60]  85.8 14.81 0 bottom
C674  0.22uF  [C603-35X45]  83.52 15.37 270 bottom
C675  0.22uF  [C603-35X45]  81.99 15.37 270 bottom
C676  0.22uF  [C603-35X45]  80.34 15.37 270 bottom
C677  0.22uF  [C603-35X45]  78.82 15.37 270 bottom
C678  10uF  [C805-35X60]  76.4 14.81 180 bottom
C679  0.22uF  [C603-35X45]  74.02 15.37 270 bottom
C680  2.2uF/0402/6.3V  [C402-25]  126.44 72.98 270 bottom
C683  100uF 10V  [C7343-84X118]  125.04 117.68 0 top
C693  0.1uF  [C402-25]  127.33 161.11 0 bottom
C696  0.1uF  [C402-25]  137.74 69.8 180 bottom
C708  2.2uF  [C402-25]  77.65 217.23 0 top
C715  680pF  [C402-25]  51.69 214.99 0 top
C716  0.1uF  [C402-25]  101.42 214.99 0 top
C717  0.1uF  [C402-25]  103.71 214.99 0 top
C718  0.1uF  [C402-25]  105.99 214.99 0 top
C719  0.1uF  [C402-25]  108.28 214.99 0 top
C720  0.1uF  [C402-25]  110.57 214.99 0 top
C721  0.1uF  [C402-25]  112.85 214.99 0 top
C733  0.1uF  [C402-25]  109.65 217.23 0 top
C734  10uF  [C603-35X45]  93.14 217.35 0 top
C735  0.1uF  [C402-25]  107.37 217.23 0 top
C785  0.1uF  [C402-25]  115.14 214.99 0 top
C786  0.01uF  [C402-25]  150.66 196.24 0 top
C787  0.1uF  [C402-25]  97.71 217.23 0 top
C788  0.1uF  [C402-25]  49.4 214.99 0 top
C789  1uF  [C402-25]  47.73 217.23 0 top
C790  1uF  [C402-25]  45.44 217.23 0 top
C791  1uF  [C402-25]  132.92 214.99 0 top
C792  0.1uF  [C402-25]  117.42 214.99 0 top
C793  0.1uF  [C402-25]  119.71 214.99 0 top
C794  2.2uF  [C402-25]  79.93 217.23 0 top
C795  330pF  [C603-35X45]  159.29 196.37 0 top
C796  330pF  [C603-35X45]  98.48 196.37 0 top
C797  0.1uF  [C402-25]  122 214.99 0 top
C798  33pF  [C402-25]  101.02 196.24 0 top
C799  33pF  [C402-25]  95.94 196.24 0 top
C800  0.1uF  [C402-25]  124.28 214.99 0 top
C801  0.1uF  [C402-25]  126.57 214.99 0 top
C810  4.7uF 10V  [C805-35X60]  75.01 217.71 0 top
D1  DIODE  [POWERMITE-CASE457-04]  104.72 197.39 0 top
D2  DIODE  [POWERMITE-CASE457-04]  115.57 197.39 0 top
E1  NFM21PC474R1C3D  [EMI-NFM21P]  37.03 73.48 90 top
E2  NFM21PC474R1C3D  [EMI-NFM21P]  40.34 73.48 90 top
E3  NFM21PC474R1C3D  [EMI-NFM21P]  43.64 73.48 90 top
E4  NFM21PC474R1C3D  [EMI-NFM21P]  82.35 196.5 0 top
E5  NFM21PC474R1C3D  [EMI-NFM21P]  89.47 196.5 0 top
E6  NFM21PC474R1C3D  [EMI-NFM21P]  85.91 196.5 0 top
E8  NFM21PC474R1C3D  [EMI-NFM21P]  126.57 60.02 270 top
E9  NFM21PC474R1C3D  [EMI-NFM21P]  41.73 52.15 180 top
E10  NFM21PC474R1C3D  [EMI-NFM21P]  78.8 196.5 0 top
E11  NFM21PC474R1C3D  [EMI-NFM21P]  93.02 196.5 0 top
F1  8A_QuickBlow  [FUSEFOLDER-OMNI-BLOK]  146.38 167.34 90 top
FL1  DLW21SN121HQ2  [EMI-36X15-DLW21]  40.97 173.56 90 top
FL4  DLW21SN121HQ2  [EMI-36X15-DLW21]  54.18 170.89 90 top
FL5  DLW21SN121HQ2  [EMI-36X15-DLW21]  12.14 167.21 90 top
J17  MIPI-QSH-030  [QSH-030-01-F]  114.76 35.13 180 top
J21  HEADER 2  [JUMP1X2-5635-2MM]  109.46 197.13 0 top
J24  HEADER 2  [JUMP1X2-5635-2MM]  120.3 197.13 0 top
L2  NP  [L603-35X45]  106.76 167.46 90 top
L3  Ferrite Chip  [L603-35X45]  103.2 160.73 0 top
L6  2.2uH ( 7443330220)  [CHOKE-POWER-WE-HCC]  137.49 124.41 270 top
L7  8.2uH(744771008 )  [IND2-115X213-12MM]  163.14 123.14 270 top
L8  BLM21PG221SN1  [L805-35X60]  33.48 92.41 270 top
L9  1uH  [IND2-65X90-IHLP1616]  122 89.61 270 top
L10  1uH  [IND2-65X90-IHLP1616]  126.57 89.61 270 top
L11  1uH  [IND2-65X90-IHLP1616]  131.14 89.61 270 top
L12  BLM21PG221SN1  [L805-35X60]  33.48 83.77 270 top
L13  1uH  [IND2-65X90-IHLP1616]  116.15 81.49 0 top
L14  1uH  [IND2-65X90-IHLP1616]  139.78 81.49 180 top
L15  1uH  [IND2-65X90-IHLP1616]  116.15 76.91 0 top
L16  1uH  [IND2-65X90-IHLP1616]  139.78 76.91 180 top
L17  1uH  [IND2-65X90-IHLP1616]  116.15 72.34 0 top
L18  1uH  [IND2-65X90-IHLP1616]  139.78 72.34 180 top
L19  BLM21PG221SN1D  [L805-35X60]  144.73 52.91 270 top
L20  1.2uH (SD12-1R2-R)  [SD12-202X60]  16.97 43.64 0 top
L21  BLM21PG221SN1D  [L805-35X60]  159.97 40.72 270 top
L22  BLM21PG221SN1D  [L805-35X60]  156.54 38.18 270 top
L23  Ferrite Chip  [L603-35X45]  100.51 217.61 0 top
L24  2.7uH  [L603-35X45]  125.51 196.62 0 top
L25  2.7uH  [L603-35X45]  128.81 196.62 0 top
NOREF  -  [unnamed]  163.65 189.05 0 top
NOREF#2  -  [#2]  36.65 184.61 0 top
NOREF#3  -  [#2]  22.56 40.21 0 top
NOREF#4  -  [#2]  0 182.7 0 top
NOREF#5  -  [unnamed]  163.65 6.35 0 top
NOREF#6  -  [#2]  5.08 177.62 0 top
NOREF#7  -  [#2]  0 195.4 0 top
NOREF#8  -  [#2]  0 12.7 0 top
NOREF#9  -  [#2]  0 0 0 top
NOREF#10  -  [#2]  0 195.4 0 top
NOREF#11  -  [#2]  0 195.4 0 top
NOREF#12  -  [#2]  2.54 15.24 0 top
NOREF#13  -  [#2]  170 0 0 top
NOREF#14  -  [#2]  170 182.7 90 top
NOREF#15  -  [#2]  0 195.4 0 top
NOREF#16  -  [#2]  -216.84 -213.08 0 top
NOREF#17  -  [unnamed]  27.76 66.5 0 top
NOREF#18  -  [#2]  0 195.4 0 top
NOREF#19  -  [#2]  2.54 15.24 0 top
NOREF#20  -  [#2]  170 12.7 90 top
NOREF#21  -  [#2]  9.35 46.81 0 top
NOREF#22  -  [#2]  164.92 177.62 90 top
NOREF#23  -  [#2]  164.92 47.78 0 top
NOREF#24  -  [#2]  170 12.7 90 top
NOREF#25  -  [#2]  30 185.24 0 top
NOREF#26  -  [unnamed]  6.35 6.35 0 top
NOREF#27  -  [unnamed]  6.35 189.05 0 top
NOREF#28  -  [#2]  9.35 46.81 0 top
NOREF#29  -  [#2]  0 195.4 0 top
NOREF#30  -  [#2]  -216.84 -213.08 0 top
NOREF#31  -  [unnamed]  6.35 6.35 180 bottom
NOREF#32  -  [unnamed]  163.65 189.05 180 bottom
NOREF#33  -  [unnamed]  163.65 6.35 180 bottom
NOREF#34  -  [unnamed]  6.35 189.05 180 bottom
NOREF#35  -  [unnamed]  167.46 171.91 180 bottom
NOREF#36  -  [unnamed]  27.76 66.5 180 bottom
P1  QSE-020-01-L-D-A-K  [QSE_020]  110.19 177.45 0 top
P5  SFM-105-02-S-D-LC  [CONN2X5-AMP104652]  30.17 199.04 0 top
P9  MEC6-150-02-S-D-RA1  [MEC6-150-RA1]  6.81 77.93 180 top
P12  Line Out  [ST_3500]  152.22 20.02 180 top
P14  MicroSD_CARD  [MOLEX-49225-201]  141.17 175.72 0 bottom
Q1  CSD18501Q5A  [PWR-Q5A-SLPS319]  143.46 135.84 0 top
Q2  CSD18501Q5A  [PWR-Q5A-SLPS319]  156.16 135.84 0 top
Q3  CSD18501Q5A  [PWR-Q5A-SLPS319]  146 132.29 180 top
Q4  CSD18501Q5A  [PWR-Q5A-SLPS319]  153.62 132.29 180 top
Q5  SUD50P04-08  [TO-252-D-PAK]  147.78 159.21 270 bottom
R1  10K  [R402-25]  47.7 173.18 270 bottom
R8  10K  [R402-25]  108.53 167.21 270 top
R9  10K  [R402-25]  115.77 166.07 90 top
R10  10K  [R402-25]  116.79 166.07 90 top
R11  10K  [R402-25]  114.25 165.56 0 top
R14  10K  [R402-25]  129.36 158.32 270 bottom
R15  10K  [R402-25]  132.92 158.32 90 bottom
R16  10K  [R402-25]  133.93 158.32 270 bottom
R17  10K  [R402-25]  137.49 158.32 90 bottom
R18  10K  [R402-25]  138.51 158.32 270 bottom
R19  10K  [R402-25]  142.06 158.32 90 bottom
R20  10K  [R402-25]  116.54 158.83 90 top
R22  NP  [R402-25]  103.58 159.34 0 top
R35  0  [R402-25]  125.43 103.58 180 bottom
R80  NP  [R201-6P6SPC]  92.53 137.49 270 top
R81  NP  [R201-6P6SPC]  93.8 137.49 270 top
R82  NP  [R201-6P6SPC]  95.07 137.49 270 top
R83  1K  [R201-6P6SPC]  96.34 137.49 270 top
R84  NP  [R201-6P6SPC]  97.61 137.49 270 top
R85  1K  [R201-6P6SPC]  98.88 137.49 270 top
R86  10K  [R201-6P6SPC]  100.15 137.49 270 top
R87  10K  [R201-6P6SPC]  101.42 137.49 270 top
R88  10K  [R201-6P6SPC]  104.72 137.49 270 top
R89  NP  [R201-6P6SPC]  105.99 137.49 270 top
R90  NP  [R201-6P6SPC]  107.26 137.49 270 top
R91  NP  [R201-6P6SPC]  108.53 137.49 270 top
R92  NP  [R201-6P6SPC]  109.8 137.49 270 top
R93  NP  [R201-6P6SPC]  111.07 137.49 270 top
R94  NP  [R201-6P6SPC]  112.34 137.49 270 top
R95  10K  [R201-6P6SPC]  113.61 137.49 270 top
R100  22  [R402-25]  60.66 129.62 270 top
R106  22  [R402-25]  13.28 138.38 180 top
R110  10K  [R201-6P6SPC]  92.53 126.04 270 top
R111  10K  [R201-6P6SPC]  93.8 126.04 270 top
R112  10K  [R201-6P6SPC]  95.07 126.04 270 top
R113  10K  [R201-6P6SPC]  96.34 126.04 270 top
R114  10K  [R201-6P6SPC]  97.61 126.04 270 top
R115  10K  [R201-6P6SPC]  98.88 126.04 270 top
R116  NP  [R201-6P6SPC]  100.15 126.04 270 top
R117  NP  [R201-6P6SPC]  101.42 126.04 270 top
R118  NP  [R201-6P6SPC]  104.72 126.04 270 top
R119  10K  [R201-6P6SPC]  105.99 126.04 270 top
R120  10K  [R201-6P6SPC]  107.26 126.04 270 top
R121  10K  [R201-6P6SPC]  108.53 126.04 270 top
R122  10K  [R201-6P6SPC]  109.8 126.04 270 top
R123  10K  [R201-6P6SPC]  111.07 126.04 270 top
R124  10K  [R201-6P6SPC]  112.34 126.04 270 top
R125  NP  [R201-6P6SPC]  113.61 126.04 270 top
R126  10  [R603-35X45]  136.47 135.84 0 top
R127  10  [R603-35X45]  164.41 135.84 180 top
R128  10K  [R402-25]  87.96 106.25 90 top
R131  10K  [R402-25]  91.01 115.01 270 top
R134  .005 OHM  [R2725-125X250]  139.4 113.62 90 top
R135  0.015  [R2512]  158.7 111.33 90 top
R138  10K  [R402-25]  155.91 109.43 270 top
R140  10K  [R402-25]  144.48 106.63 270 top
R143  49.9  [R603-35X45]  138.51 104.73 0 top
R144  49.9K 1%  [R402-25]  138.51 106.63 180 top
R145  16.0K 1%  [R603-35X45]  152.86 104.73 0 top
R146  84.5K 1%  [R603-35X45]  156.41 104.73 0 top
R147  49.9  [R603-35X45]  156.41 102.82 180 top
R151  0  [R402-25]  136.6 91.77 0 top
R152  10K  [R402-25]  138.89 91.77 0 top
R153  10K  [R402-25]  135.2 89.49 270 top
R154  100K  [R402-25]  33.48 89.87 0 top
R157  NP  [R402-25]  20.4 83.64 90 top
R178  NP  [R402-25]  18.87 81.61 270 top
R179  100K  [R402-25]  33.48 81.23 0 top
R182  100  [R402-25]  114.1 217.23 0 top
R183  100  [R402-25]  118.16 217.23 0 top
R184  100  [R402-25]  116.13 217.23 0 top
R191  NP  [R402-25]  119.33 68.4 180 top
R192  0  [R402-25]  123.14 68.4 90 top
R193  0  [R402-25]  126.7 68.4 90 top
R194  NP  [R201-6P6SPC]  120.98 67.77 90 top
R196  NP  [R402-25]  20.4 68.02 90 top
R200  NP  [R402-25]  18.87 65.99 270 top
R204  NP  [R201-6P6SPC]  44.78 64.09 270 bottom
R205  10K  [R201-6P6SPC]  120.98 64.72 270 top
R206  NP  [R201-6P6SPC]  122.12 64.72 270 top
R207  0  [R201-6P6SPC]  123.27 64.72 90 top
R208  NP  [R201-6P6SPC]  124.41 64.72 90 top
R209  NP  [R201-6P6SPC]  126.7 64.72 90 top
R210  10K  [R201-6P6SPC]  127.71 64.72 90 top
R211  1.2K  [R201-6P6SPC]  128.73 64.72 90 top
R216  0  [R201-6P6SPC]  45.92 62.94 0 bottom
R222  0  [R402-25]  13.16 60.28 90 top
R232  10  [R402-25]  37.19 217.23 0 top
R238  62  [R1206-40X70]  20.78 56.97 270 top
R241  4.99K 1%  [R603-35X45]  6.17 56.09 90 top
R244  17.4K  [R603-35X45]  3.25 55.32 0 top
R245  NP  [R201-6P6SPC]  55.91 214.76 0 top
R249  NP  [R402-25]  150.32 52.15 270 top
R250  10  [R402-25]  151.59 52.15 270 top
R251  10  [R402-25]  152.86 52.15 270 top
R252  10  [R402-25]  154.13 52.15 270 top
R253  10  [R402-25]  155.4 52.15 270 top
R254  22  [R402-25]  156.67 52.15 270 top
R255  62  [R1206-40X70]  20.78 51.89 270 top
R256  2.2K  [R402-25]  122.22 217.23 0 top
R257  2.2K  [R402-25]  141.3 50.75 180 top
R260  2.2K  [R402-25]  141.3 49.61 180 top
R262  NP  [R402-25]  141.3 48.47 180 top
R266  NP  [R402-25]  141.3 47.32 180 top
R269  0  [R201-6P6SPC]  17.09 216.99 0 top
R272  10K  [R402-25]  4.9 41.73 0 top
R273  10K  [R402-25]  2.11 40.72 0 top
R276  NP  [R603-35X45]  14.68 38.18 90 top
R277  86.6K 1%  [R402-25]  11.63 35.77 180 top
R278  16.0K 1%  [R603-35X45]  6.17 35 90 top
R279  11.0K 1%  [R402-25]  7.44 35 270 top
R280  12k  [R402-25]  8.71 35 270 top
R281  100  [R402-25]  155.65 32.72 180 top
R282  100K  [R402-25]  6.17 31.57 90 top
R283  10K  [R402-25]  7.44 31.57 90 top
R286  49.9/1%  [R402-25]  105.56 29.16 0 top
R287  20K  [R402-25]  155.65 28.53 0 top
R288  240  [R402-25]  87.71 25.99 90 top
R289  240  [R402-25]  101.8 25.99 90 top
R290  10  [R402-25]  9.35 25.22 180 top
R291  10.0K 1%  [R402-25]  2.36 24.59 0 top
R292  10.0K 1%  [R402-25]  4.9 24.59 0 top
R301  10K  [R402-25]  45.42 173.18 270 bottom
R302  10K  [R402-25]  61.54 177.75 90 bottom
R307  10K  [R402-25]  60.53 172.54 270 bottom
R327  10K  [R402-25]  140.41 168.99 270 top
R332  10K  [R402-25]  104.98 165.31 0 bottom
R333  NP  [R402-25]  106.76 163.53 270 bottom
R338  NP  [R402-25]  116.54 159.72 270 bottom
R340  33  [R402-25]  130.12 155.65 0 bottom
R341  33  [R402-25]  140.79 155.15 90 bottom
R342  33  [R402-25]  139.78 155.15 90 bottom
R343  33  [R402-25]  136.22 155.15 90 bottom
R344  33  [R402-25]  135.2 155.15 90 bottom
R345  33  [R402-25]  131.65 155.15 90 bottom
R404  NP  [R402-25]  129.36 137.62 270 bottom
R405  NP  [R402-25]  128.09 137.62 270 bottom
R406  NP  [R402-25]  126.82 137.62 270 bottom
R407  0  [R402-25]  119.58 136.73 90 bottom
R410  49.9K 1%  [R402-25]  122.63 135.97 270 bottom
R414  NP  [R402-25]  131.39 135.46 180 bottom
R417  0  [R402-25]  123.77 134.95 270 bottom
R420  0  [R402-25]  8.97 144.73 90 bottom
R422  NP  [R402-25]  131.39 134.19 180 bottom
R423  NP  [R402-25]  131.39 132.92 180 bottom
R426  NP  [R402-25]  131.39 131.65 180 bottom
R428  NP  [R402-25]  131.39 130.38 180 bottom
R429  0  [R402-25]  124.16 129.87 270 bottom
R433  NP  [R402-25]  119.58 129.36 180 bottom
R442  10K  [R402-25]  77.67 119.71 270 top
R450  0  [R402-25]  158.57 135.59 0 bottom
R451  0  [R402-25]  143.84 135.59 180 bottom
R453  1.5K  [R603-35X45]  146.63 123.27 0 bottom
R454  NP  [R402-25]  152.35 120.6 90 bottom
R455  0  [R402-25]  151.21 120.6 270 bottom
R456  0  [R402-25]  152.1 132.29 0 bottom
R457  0  [R402-25]  144.09 131.78 270 bottom
R461  20K  [R402-25]  158.7 111.33 180 bottom
R463  0  [R402-25]  153.62 110.82 0 bottom
R464  15K  [R402-25]  142.7 110.44 90 bottom
R472  16.0K 1%  [R603-35X45]  142.06 106.63 180 top
R473  10K  [R402-25]  122.5 107.9 90 bottom
R481  10K  [R402-25]  23.32 88.6 180 bottom
R483  NP  [R201-6P6SPC]  124.54 84.79 180 bottom
R494  10  [R402-25]  18.9 217.23 0 top
R495  10  [R402-25]  20.93 217.23 0 top
R513  10K  [R402-25]  127.84 84.41 90 bottom
R514  NP  [R402-25]  126.82 84.41 270 bottom
R515  0  [R402-25]  14.68 84.53 90 bottom
R516  10K  [R201-6P6SPC]  124.92 83.77 90 bottom
R518  10K  [R402-25]  134.44 82.12 90 bottom
R519  10K  [R402-25]  20.4 82.63 90 bottom
R520  10K  [R402-25]  7.82 81.99 270 bottom
R521  10K  [R402-25]  6.81 81.99 270 bottom
R522  10K  [R402-25]  5.79 81.99 270 bottom
R523  10K  [R402-25]  4.78 81.99 270 bottom
R524  10K  [R402-25]  3.76 81.99 270 bottom
R528  10K  [R402-25]  18.87 81.61 90 bottom
R529  10K  [R402-25]  42.49 81.36 0 bottom
R530  10K  [R402-25]  44.02 80.34 0 bottom
R531  0  [R402-25]  41.61 80.34 180 bottom
R532  10K  [R402-25]  23.32 79.96 180 bottom
R533  NP  [R201-6P6SPC]  125.81 80.98 0 bottom
R534  10K  [R201-6P6SPC]  126.7 77.93 0 bottom
R535  10K  [R201-6P6SPC]  125.17 77.93 180 bottom
R537  NP  [R201-6P6SPC]  127.84 76.79 270 bottom
R548  0  [R402-25]  20.78 72.6 90 bottom
R549  0  [R201-6P6SPC]  131.65 72.21 180 bottom
R554  0  [R402-25]  110.31 70.44 270 bottom
R555  NP  [R402-25]  109.04 70.44 270 bottom
R558  20K  [R402-25]  3.63 69.67 90 bottom
R559  20K  [R402-25]  7.7 69.29 90 bottom
R560  20K  [R402-25]  6.68 69.29 90 bottom
R561  20K  [R402-25]  5.66 69.29 90 bottom
R562  20K  [R402-25]  4.65 69.29 90 bottom
R565  10K  [R201-6P6SPC]  125.5 73.41 270 bottom
R567  NP  [R402-25]  119.33 68.4 0 bottom
R569  NP  [R201-6P6SPC]  167.97 68.4 0 bottom
R570  NP  [R201-6P6SPC]  120.98 67.77 270 bottom
R573  NP  [R402-25]  163.4 67.77 270 bottom
R574  NP  [R402-25]  162.38 67.77 90 bottom
R575  NP  [R402-25]  161.37 67.77 270 bottom
R576  0  [R402-25]  160.35 67.77 90 bottom
R577  NP  [R402-25]  159.33 67.77 270 bottom
R578  0  [R402-25]  158.32 67.77 90 bottom
R581  10K  [R402-25]  20.4 67.01 90 bottom
R583  10K  [R402-25]  106.5 65.99 270 bottom
R584  10K  [R402-25]  18.87 65.99 90 bottom
R587  NP  [R402-25]  7.82 65.74 0 bottom
R588  2.2K  [R402-25]  128.73 64.72 270 bottom
R589  NP  [R201-6P6SPC]  127.71 64.72 270 bottom
R590  10K  [R201-6P6SPC]  126.7 64.72 270 bottom
R591  0  [R201-6P6SPC]  125.55 64.72 270 bottom
R592  NP  [R201-6P6SPC]  124.41 64.72 270 bottom
R593  2.2K  [R402-25]  16.33 64.85 180 bottom
R596  10K  [R402-25]  110.57 63.96 0 bottom
R597  2.2K  [R402-25]  16.33 63.58 180 bottom
R599  NP  [R201-6P6SPC]  167.97 63.32 0 bottom
R600  0  [R402-25]  18.87 63.07 180 bottom
R603  4.7K  [R402-25]  16.84 61.17 270 bottom
R605  10K  [R201-6P6SPC]  39.07 52.4 90 bottom
R615  10K  [R402-25]  16.33 57.74 90 bottom
R617  NP  [R402-25]  9.22 57.61 0 bottom
R618  2.2K  [R402-25]  126.29 217.23 0 top
R620  10K  [R201-6P6SPC]  38.43 56.47 180 bottom
R623  10K  [R402-25]  122.5 55.58 0 bottom
R624  2.2K  [R402-25]  135.18 217.23 0 top
R625  0  [R402-25]  43.28 217.23 0 top
R627  22  [R402-25]  141.17 214.99 0 top
R629  NP  [R402-25]  135.8 196.24 0 top
R632  10K  [R201-6P6SPC]  81.66 214.76 0 top
R633  2.2K  [R402-25]  124.26 217.23 0 top
R634  22  [R402-25]  143.21 214.99 0 top
R635  22  [R402-25]  145.24 214.99 0 top
R636  10K  [R201-6P6SPC]  33.48 52.66 90 bottom
R642  20K  [R402-25]  155.4 52.15 90 bottom
R643  20K  [R402-25]  152.86 52.15 90 bottom
R644  2.2K  [R402-25]  150.32 52.15 90 bottom
R650  NP  [R402-25]  133.76 196.24 0 top
R651  10  [R402-25]  39.22 217.23 0 top
R652  2.2K  [R402-25]  95.55 217.23 0 top
R653  22  [R402-25]  147.27 214.99 0 top
R654  NP  [R402-25]  141.3 50.75 0 bottom
R659  NP  [R402-25]  141.3 49.61 0 bottom
R664  NP  [R402-25]  141.3 48.47 0 bottom
R668  NP  [R402-25]  141.3 47.32 0 bottom
R671  0  [R402-25]  141.05 44.15 0 bottom
R672  2.2K  [R402-25]  141.05 43 0 bottom
R673  330  [R402-25]  138.51 43 0 bottom
R675  NP  [R402-25]  141.05 40.72 0 bottom
R684  49.9/1%  [R402-25]  64.29 30.81 0 bottom
R685  49.9/1%  [R402-25]  105.56 30.3 0 bottom
R687  49.9/1%  [R402-25]  64.29 29.67 0 bottom
R688  49.9/1%  [R402-25]  105.56 29.16 0 bottom
R689  49.9-1%  [R402-25]  64.29 28.65 0 bottom
R691  240  [R402-25]  46.51 24.97 180 bottom
R692  240  [R402-25]  33.81 24.97 180 bottom
R693  240  [R402-25]  60.3 24.56 0 bottom
R694  240  [R402-25]  89.51 23.7 270 bottom
R695  240  [R402-25]  75.16 23.7 270 bottom
R697  100  [R402-25]  148.54 23.57 270 bottom
R702  20K  [R402-25]  148.03 17.86 180 bottom
R708  NP  [R201-6P6SPC]  133.05 81.99 180 bottom
R709  NP  [R201-6P6SPC]  129.49 79.71 270 bottom
R714  0  [R201-6P6SPC]  19.51 74.25 90 top
R715  0  [R201-6P6SPC]  12.9 96.34 90 top
R727  10  [R402-25]  73.86 107.9 180 top
R728  10  [R402-25]  76.02 107.9 180 top
R757  10K  [R201-6P6SPC]  160.99 55.45 90 bottom
R758  0  [R402-25]  120.09 32.08 90 bottom
R759  4.7K  [R402-25]  123.39 34.37 90 bottom
R760  4.7K  [R402-25]  122.25 34.37 270 bottom
R761  0  [R402-25]  121.36 32.08 90 bottom
R762  0  [R402-25]  118.82 40.97 270 top
R766  10K  [R201-6P6SPC]  158.57 63.2 0 top
R770  10K  [R402-25]  134.19 46.69 180 bottom
R771  10K  [R402-25]  134.19 45.42 180 bottom
R774  0  [R603-35X45]  121.36 158.32 90 bottom
R782  0  [R402-25]  140.28 66.63 270 bottom
R783  NP  [R402-25]  142.82 66.63 270 bottom
R784  NP  [R402-25]  141.55 66.63 270 bottom
R785  NP  [R402-25]  57.71 214.99 0 top
R800  NP  [R402-25]  165.57 196.24 0 top
R801  0  [R402-25]  120.19 217.23 0 top
R802  NP  [R402-25]  167.6 196.24 0 top
R828  4.7K  [R402-25]  82.09 217.23 0 top
R829  4.7K  [R402-25]  84.12 217.23 0 top
R830  1K  [R402-25]  1.07 214.99 0 top
R831  10K ???  [R402-25]  3.1 214.99 0 top
R832  10K  [R402-25]  95.2 214.99 0 top
R834  10  [R402-25]  22.96 217.23 0 top
R835  10  [R402-25]  24.99 217.23 0 top
R836  10  [R402-25]  27.03 217.23 0 top
R837  10  [R402-25]  29.06 217.23 0 top
R838  10K  [R402-25]  93.17 214.99 0 top
R839  NP  [R402-25]  137.83 196.24 0 top
R840  NP  [R402-25]  139.86 196.24 0 top
R841  NP  [R402-25]  141.89 196.24 0 top
R842  0  [R402-25]  151.33 214.99 0 top
R843  0  [R402-25]  153.37 214.99 0 top
R844  0  [R402-25]  155.4 214.99 0 top
R845  0  [R402-25]  157.43 214.99 0 top
R846  0  [R402-25]  159.46 214.99 0 top
R848  NP  [R402-25]  143.92 196.24 0 top
R849  10K  [R402-25]  91.14 214.99 0 top
R850  0  [R402-25]  161.49 214.99 0 top
R851  0  [R402-25]  163.53 214.99 0 top
R859  22  [R402-25]  128.73 214.99 0 top
R864  0  [R402-25]  165.56 214.99 0 top
R865  0  [R402-25]  167.59 214.99 0 top
R866  2.2K  [R402-25]  103.17 217.23 0 top
R867  2.2K  [R402-25]  105.21 217.23 0 top
R911  4.7K  [R402-25]  86.16 217.23 0 top
R912  0  [R402-25]  1.07 217.23 0 top
R913  0  [R402-25]  3.1 217.23 0 top
R914  10K  [R201-6P6SPC]  83.24 214.76 0 top
R915  NP  [R201-6P6SPC]  163.76 196.01 0 top
R917  10  [R402-25]  97.23 214.99 0 top
R918  10  [R402-25]  99.26 214.99 0 top
R919  10  [R402-25]  77.83 214.99 0 top
R920  10  [R402-25]  79.86 214.99 0 top
R921  10  [R402-25]  49.89 217.23 0 top
R922  10  [R402-25]  51.92 217.23 0 top
R923  10  [R402-25]  53.95 217.23 0 top
R924  10  [R402-25]  55.98 217.23 0 top
R925  10  [R402-25]  58.01 217.23 0 top
R926  10  [R402-25]  41.25 217.23 0 top
R927  10  [R402-25]  62.33 217.23 0 top
R928  10  [R402-25]  64.36 217.23 0 top
R929  10  [R402-25]  66.4 217.23 0 top
R930  10  [R402-25]  68.43 217.23 0 top
R931  10  [R402-25]  70.46 217.23 0 top
R933  0  [R402-25]  5.13 217.23 0 top
R934  NP  [R402-25]  47.24 214.99 0 top
R935  0  [R402-25]  7.16 217.23 0 top
R936  NP  [R402-25]  70.76 214.99 0 top
R937  0  [R402-25]  9.19 217.23 0 top
R938  NP  [R402-25]  68.73 214.99 0 top
R939  NP  [R402-25]  152.81 196.24 0 top
R940  0  [R402-25]  11.23 217.23 0 top
R941  0  [R402-25]  13.26 217.23 0 top
R942  0  [R402-25]  15.29 217.23 0 top
R943  226  [R603-35X45]  5.77 215.37 0 top
R944  10K  [R402-25]  89.1 214.99 0 top
R945  10K  [R402-25]  87.07 214.99 0 top
R946  NP  [R402-25]  154.85 196.24 0 top
R947  22  [R402-25]  130.76 214.99 0 top
R948  22  [R402-25]  75.79 214.99 0 top
R949  22  [R402-25]  135.08 214.99 0 top
R950  22  [R402-25]  137.11 214.99 0 top
R951  56  [R603-35X45]  12.37 215.37 0 top
R952  0  [R402-25]  15.04 214.99 0 top
R953  226  [R603-35X45]  9.07 215.37 0 top
R954  75  [R603-35X45]  19.74 215.37 0 top
R955  0  [R402-25]  17.07 214.99 0 top
R956  100K  [R402-25]  22.4 214.99 0 top
R957  22  [R402-25]  139.14 214.99 0 top
R958  10K  [R402-25]  85.04 214.99 0 top
R959  NP  [R402-25]  156.88 196.24 0 top
R960  10  [R402-25]  31.09 217.23 0 top
R961  10  [R402-25]  33.12 217.23 0 top
R962  10  [R402-25]  35.15 217.23 0 top
R963  0  [R402-25]  149.3 214.99 0 top
R?  1K  [R402-25]  72.49 217.23 0 top
RN2  R-PACK4-47  [RPAK8-10X25-28V]  64.54 26.75 270 top
RN3  R-PACK4-47  [RPAK8-10X25-28V]  105.82 26.75 270 top
RN4  R-PACK4-47  [RPAK8-10X25-28V]  64.54 23.32 270 top
RN5  R-PACK4-47  [RPAK8-10X25-28V]  105.82 23.32 270 top
RN6  R-PACK4-47  [RPAK8-10X25-28V]  64.54 19.89 270 top
RN7  R-PACK4-47  [RPAK8-10X25-28V]  105.82 19.89 270 top
RN12  R-PACK4-47  [RPAK8-10X25-28V]  105.82 26.75 90 bottom
RN13  R-PACK4-47  [RPAK8-10X25-28V]  64.54 26.75 90 bottom
RN14  R-PACK4-47  [RPAK8-10X25-28V]  105.82 23.32 90 bottom
RN15  R-PACK4-47  [RPAK8-10X25-28V]  64.54 23.32 90 bottom
RN16  R-PACK4-47  [RPAK8-10X25-28V]  105.82 19.89 90 bottom
RN17  R-PACK4-47  [RPAK8-10X25-28V]  64.54 19.89 90 bottom
RN20  RPACK4-10  [RPAK8-10X25-28V]  61.23 196.88 0 top
RN21  RPACK4-10  [RPAK8-10X25-28V]  58.31 196.88 0 top
RN22  RPACK4-10  [RPAK8-10X25-28V]  55.39 196.88 0 top
RN23  RPACK4-10  [RPAK8-10X25-28V]  49.54 196.88 0 top
RN24  RPACK4-10  [RPAK8-10X25-28V]  52.46 196.88 0 top
RN25  RPACK4-10  [RPAK8-10X25-28V]  46.62 196.88 0 top
RN30  RPACK4-10  [RPAK8-10X25-28V]  37.86 196.88 0 top
RN31  RPACK4-10  [RPAK8-10X25-28V]  43.7 196.88 0 top
RN32  RPACK4-10  [RPAK8-10X25-28V]  40.78 196.88 0 top
RN33  RPACK4-10  [RPAK8-10X25-28V]  64.15 196.88 0 top
SW4  PB_SW  [SW4-7914G]  109.04 67.9 0 top
TP1  NP  [TP20]  60.27 177.5 0 top
